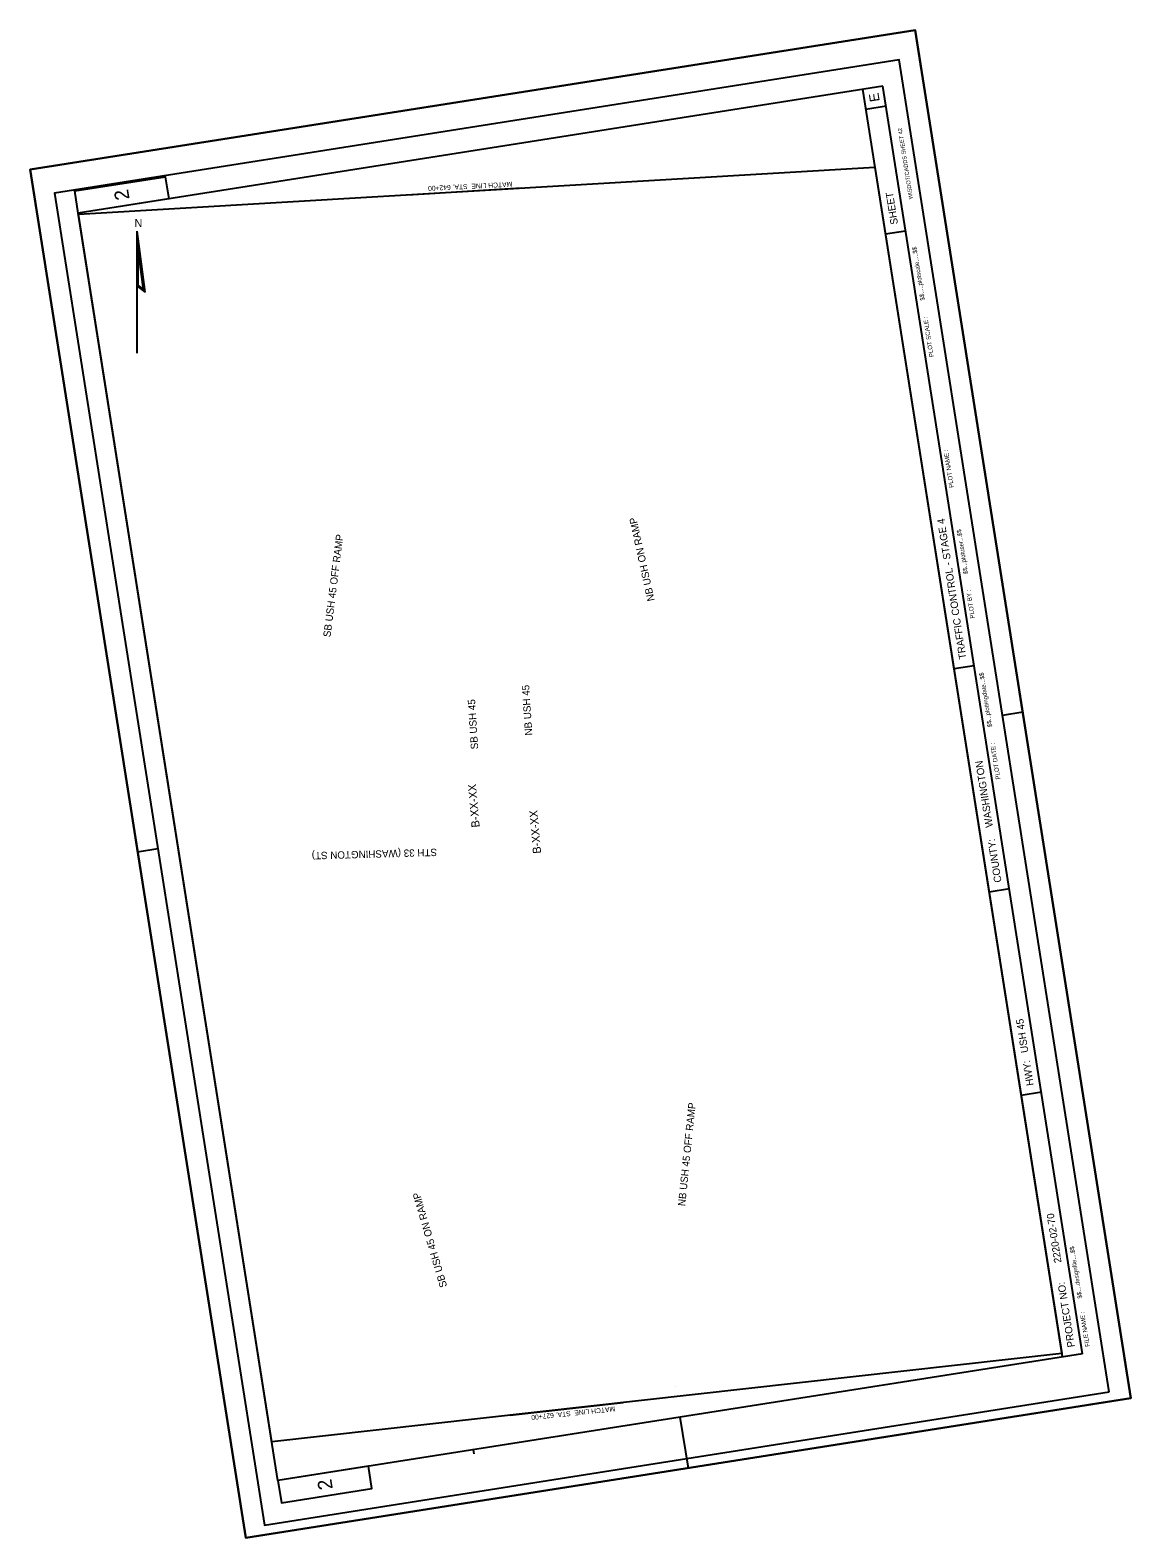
# Model space of a CAD drawing. Extents: x 355023 to 356374, y 184746 to 186597.
import ezdxf

# ---------------------------------------------------------------- set-up
doc = ezdxf.new("R2010")
doc.units = 0
for name, color, linetype in [('Default', 7, 'Continuous'), ('P_ALI_100_PIData', 7, 'Continuous'), ('P_ALI_20', 7, 'Continuous'), ('P_ALI_200_Equation', 7, 'Continuous'), ('P_ALI_20_Equation', 7, 'Continuous'), ('P_ALI_20_PIData', 7, 'Continuous'), ('P_ALI_20_Sta', 7, 'Continuous'), ('P_ALI_20_Tic', 7, 'Continuous')]:
    doc.layers.add(name, color=color, linetype=linetype)

msp = doc.modelspace()

# ---------------------------------------------------------------- linework, layer by layer
for p, q in [((356109.4, 186597), (356060, 186589.2)), ((356117.2, 186547.6), (356109.4, 186597)), ((356069.6, 186528.2), (355081.8, 186372.6)), ((356290.1, 184968.6), (356044.9, 186524.4)), ((356314.8, 184972.5), (356069.6, 186528.2)), ((356073.5, 186503.6), (356048.8, 186499.7)), ((355072.2, 186433.6), (355022.8, 186425.8)), ((355030.6, 186376.4), (355022.8, 186425.8)), ((355327, 184816.8), (355081.8, 186372.6)), ((356097.6, 186350.4), (356072.9, 186346.6)), ((356181.7, 185817), (356157, 185813.1)), ((356245.2, 185735.2), (356237.4, 185784.6)), ((356241.3, 185759.9), (356216.6, 185756)), ((355158.6, 185563.9), (355150.8, 185613.3)), ((355154.7, 185588.6), (355179.4, 185592.5)), ((356224.9, 185542.9), (356200.2, 185539)), ((356264.2, 185293.5), (356239.5, 185289.6)), ((356314.8, 184972.5), (355327, 184816.8)), ((356374, 184917.8), (356366.3, 184967.2)), ((355815.1, 184931.7), (355815.1, 184931.7)), ((356374, 184917.8), (356324.7, 184910)), ((355830.8, 184832.1), (355820.9, 184894.6)), ((355566.5, 184854.5), (355567.3, 184849.6)), ((355855.5, 184836), (355806.1, 184828.2)), ((355287.5, 184746.5), (355279.7, 184795.9)), ((355336.9, 184754.3), (355287.5, 184746.5))]:
    msp.add_line(p, q)
for points in [[(355081.8, 186372.6), (355077.5, 186399.7), (355188.6, 186417.2), (355192.9, 186390.1)], [(355327, 184816.8), (355331.3, 184789.6), (355442.4, 184807.1), (355438.1, 184834.3)]]:
    msp.add_lwpolyline(points, close=True)
at = {"layer": 'Default'}
msp.add_lwpolyline([(355082, 186371.2), (356059.9, 186428.9), (356289.5, 184972.6), (355319.5, 184864.4)], close=True, dxfattribs=at)
msp.add_lwpolyline([(355082, 186371.2), (356059.9, 186428.9), (356289.5, 184972.6), (355319.5, 184864.4)], close=True, dxfattribs=at)
msp.add_lwpolyline([(355082, 186371.2), (356059.9, 186428.9), (356289.5, 184972.6), (355319.5, 184864.4)], close=True, dxfattribs=at)
at = {"layer": 'P_ALI_100_PIData'}
msp.add_lwpolyline([(355287.5, 184746.5), (355022.8, 186425.8), (356109.4, 186597), (356374, 184917.8)], close=True, dxfattribs=at)
at = {"layer": 'P_ALI_20'}
for points in [[(356374, 184917.8), (356109.4, 186597), (355022.8, 186425.8), (355287.5, 184746.5)], [(356347.5, 184925.7), (356089.8, 186560.5), (355052.6, 186397.1), (355310.3, 184762.2)]]:
    msp.add_lwpolyline(points, close=True, dxfattribs=at)
at = {"layer": 'P_ALI_200_Equation'}
msp.add_lwpolyline([(355287.5, 184746.5), (355022.8, 186425.8), (356109.4, 186597), (356374, 184917.8), (355287.5, 184746.5)], dxfattribs=at)
at = {"layer": 'P_ALI_20_Equation'}
for p, q in [((355164, 186275.4), (355154, 186350.4)), ((355154, 186282.9), (355154, 186350.4)), ((355154.8, 186283.2), (355154.8, 186339.1)), ((355163, 186277), (355154.8, 186339.1)), ((355155.5, 186283.6), (355155.5, 186327.8)), ((355162.1, 186278.7), (355155.5, 186327.8)), ((355154, 186282.9), (355164, 186275.4)), ((355154, 186200.4), (355154, 186282.9)), ((355154.3, 186200.4), (355154.3, 186282.7)), ((355154.8, 186283.2), (355163, 186277)), ((355155.5, 186283.6), (355162.1, 186278.7))]:
    msp.add_line(p, q, dxfattribs=at)
msp.add_lwpolyline([(355154, 186350.3), (355154, 186350.3)], dxfattribs=at)
at = {"layer": 'P_ALI_20_Sta'}
for p, q in [((355486.6, 186395.1), (355625.6, 186403.3)), ((355612.2, 184897.1), (355750.7, 184912.5))]:
    msp.add_line(p, q, dxfattribs=at)

# ---------------------------------------------------------------- texts
for s, height, p in [('E', 12, (356065.8, 186510)), ('WISDOT/CADDS SHEET 42', 5, (356106.6, 186390)), ('2', 17.5, (355144.9, 186389.8)), ('SHEET ', 9, (356088.2, 186359.1)), ('$$.....plotscale.....$$', 5.4, (356121.1, 186265.6)), ('PLOT SCALE : ', 5.4, (356132, 186196.2)), ('PLOT NAME :                      ', 5.4, (356156.8, 186035.8)), ('TRAFFIC CONTROL - STAGE 4', 9, (356172.2, 185825.7)), ('$$...plotuser...$$', 5.4, (356174.1, 185929.7)), ('PLOT BY :', 5.4, (356182.6, 185875.4)), ('$$...plottingdate...$$', 5.4, (356203.6, 185742)), ('PLOT DATE :', 5.4, (356213.8, 185677.8)), (' WASHINGTON', 9, (356205.3, 185615.8)), ('COUNTY:', 9, (356215.4, 185551.5)), (' USH 45', 9, (356248.9, 185339.2)), ('HWY:', 9, (356254.8, 185302.1)), (' 2220-02-70', 9, (356289.5, 185081.3)), ('$$....designfile....$$', 5.4, (356314.2, 185040.7)), ('PROJECT NO:', 9, (356305.4, 184981.1)), ('FILE NAME :', 5.4, (356323.5, 184981.4)), ('2', 17.5, (355394.4, 184806.8))]:
    msp.add_text(s, height=height, rotation=98.957).set_placement(p)
at = {"layer": 'P_ALI_20_Equation'}
msp.add_text('N', height=10, dxfattribs=at).set_placement((355150.9, 186355.3))
at = {"layer": 'P_ALI_20_PIData'}
for p in [(355574.7, 185618.8), (355650.1, 185586.7)]:
    msp.add_text('B-XX-XX', height=10, rotation=94.9466, dxfattribs=at).set_placement(p)
at = {"layer": 'P_ALI_20_Tic'}
for s, height, rotation, p in [('MATCH LINE  STA. 642+00', 6, 182.9694, (355614.4, 186411)), ('NB USH ON RAMP', 9, 102.3756, (355789.5, 185897.2)), ('SB USH 45 OFF RAMP', 9, 82.7573, (355391.4, 185851.6)), ('SB USH 45', 9, 93.7302, (355572.9, 185714.6)), ('NB USH 45', 9, 93.7302, (355639.4, 185731.6)), ('STH 33 (WASHINGTON ST)', 9, 181.5874, (355522.1, 185592.4)), ('NB USH 45 OFF RAMP', 9, 84.1248, (355826.9, 185153.3)), ('SB USH 45 ON RAMP', 9, 106.2703, (355534.8, 185055.2)), ('MATCH LINE  STA. 627+00', 6, 185.9528, (355740.5, 184907.8))]:
    msp.add_text(s, height=height, rotation=rotation, dxfattribs=at).set_placement(p)

doc.saveas('drawing.dxf')
